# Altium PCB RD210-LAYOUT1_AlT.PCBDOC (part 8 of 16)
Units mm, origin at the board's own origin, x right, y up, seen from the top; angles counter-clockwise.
Board outline 330 x 300 mm, 6 copper layers (TOP, Mid-Layer 1, Mid-Layer 2, Mid-Layer 3, Mid-Layer 4, BOTTOM), stack 1.422 mm thick; 981 components, 463 nets, 2326 pads, 12534 vias.
Unrouted connection lines stored in the file: 6.
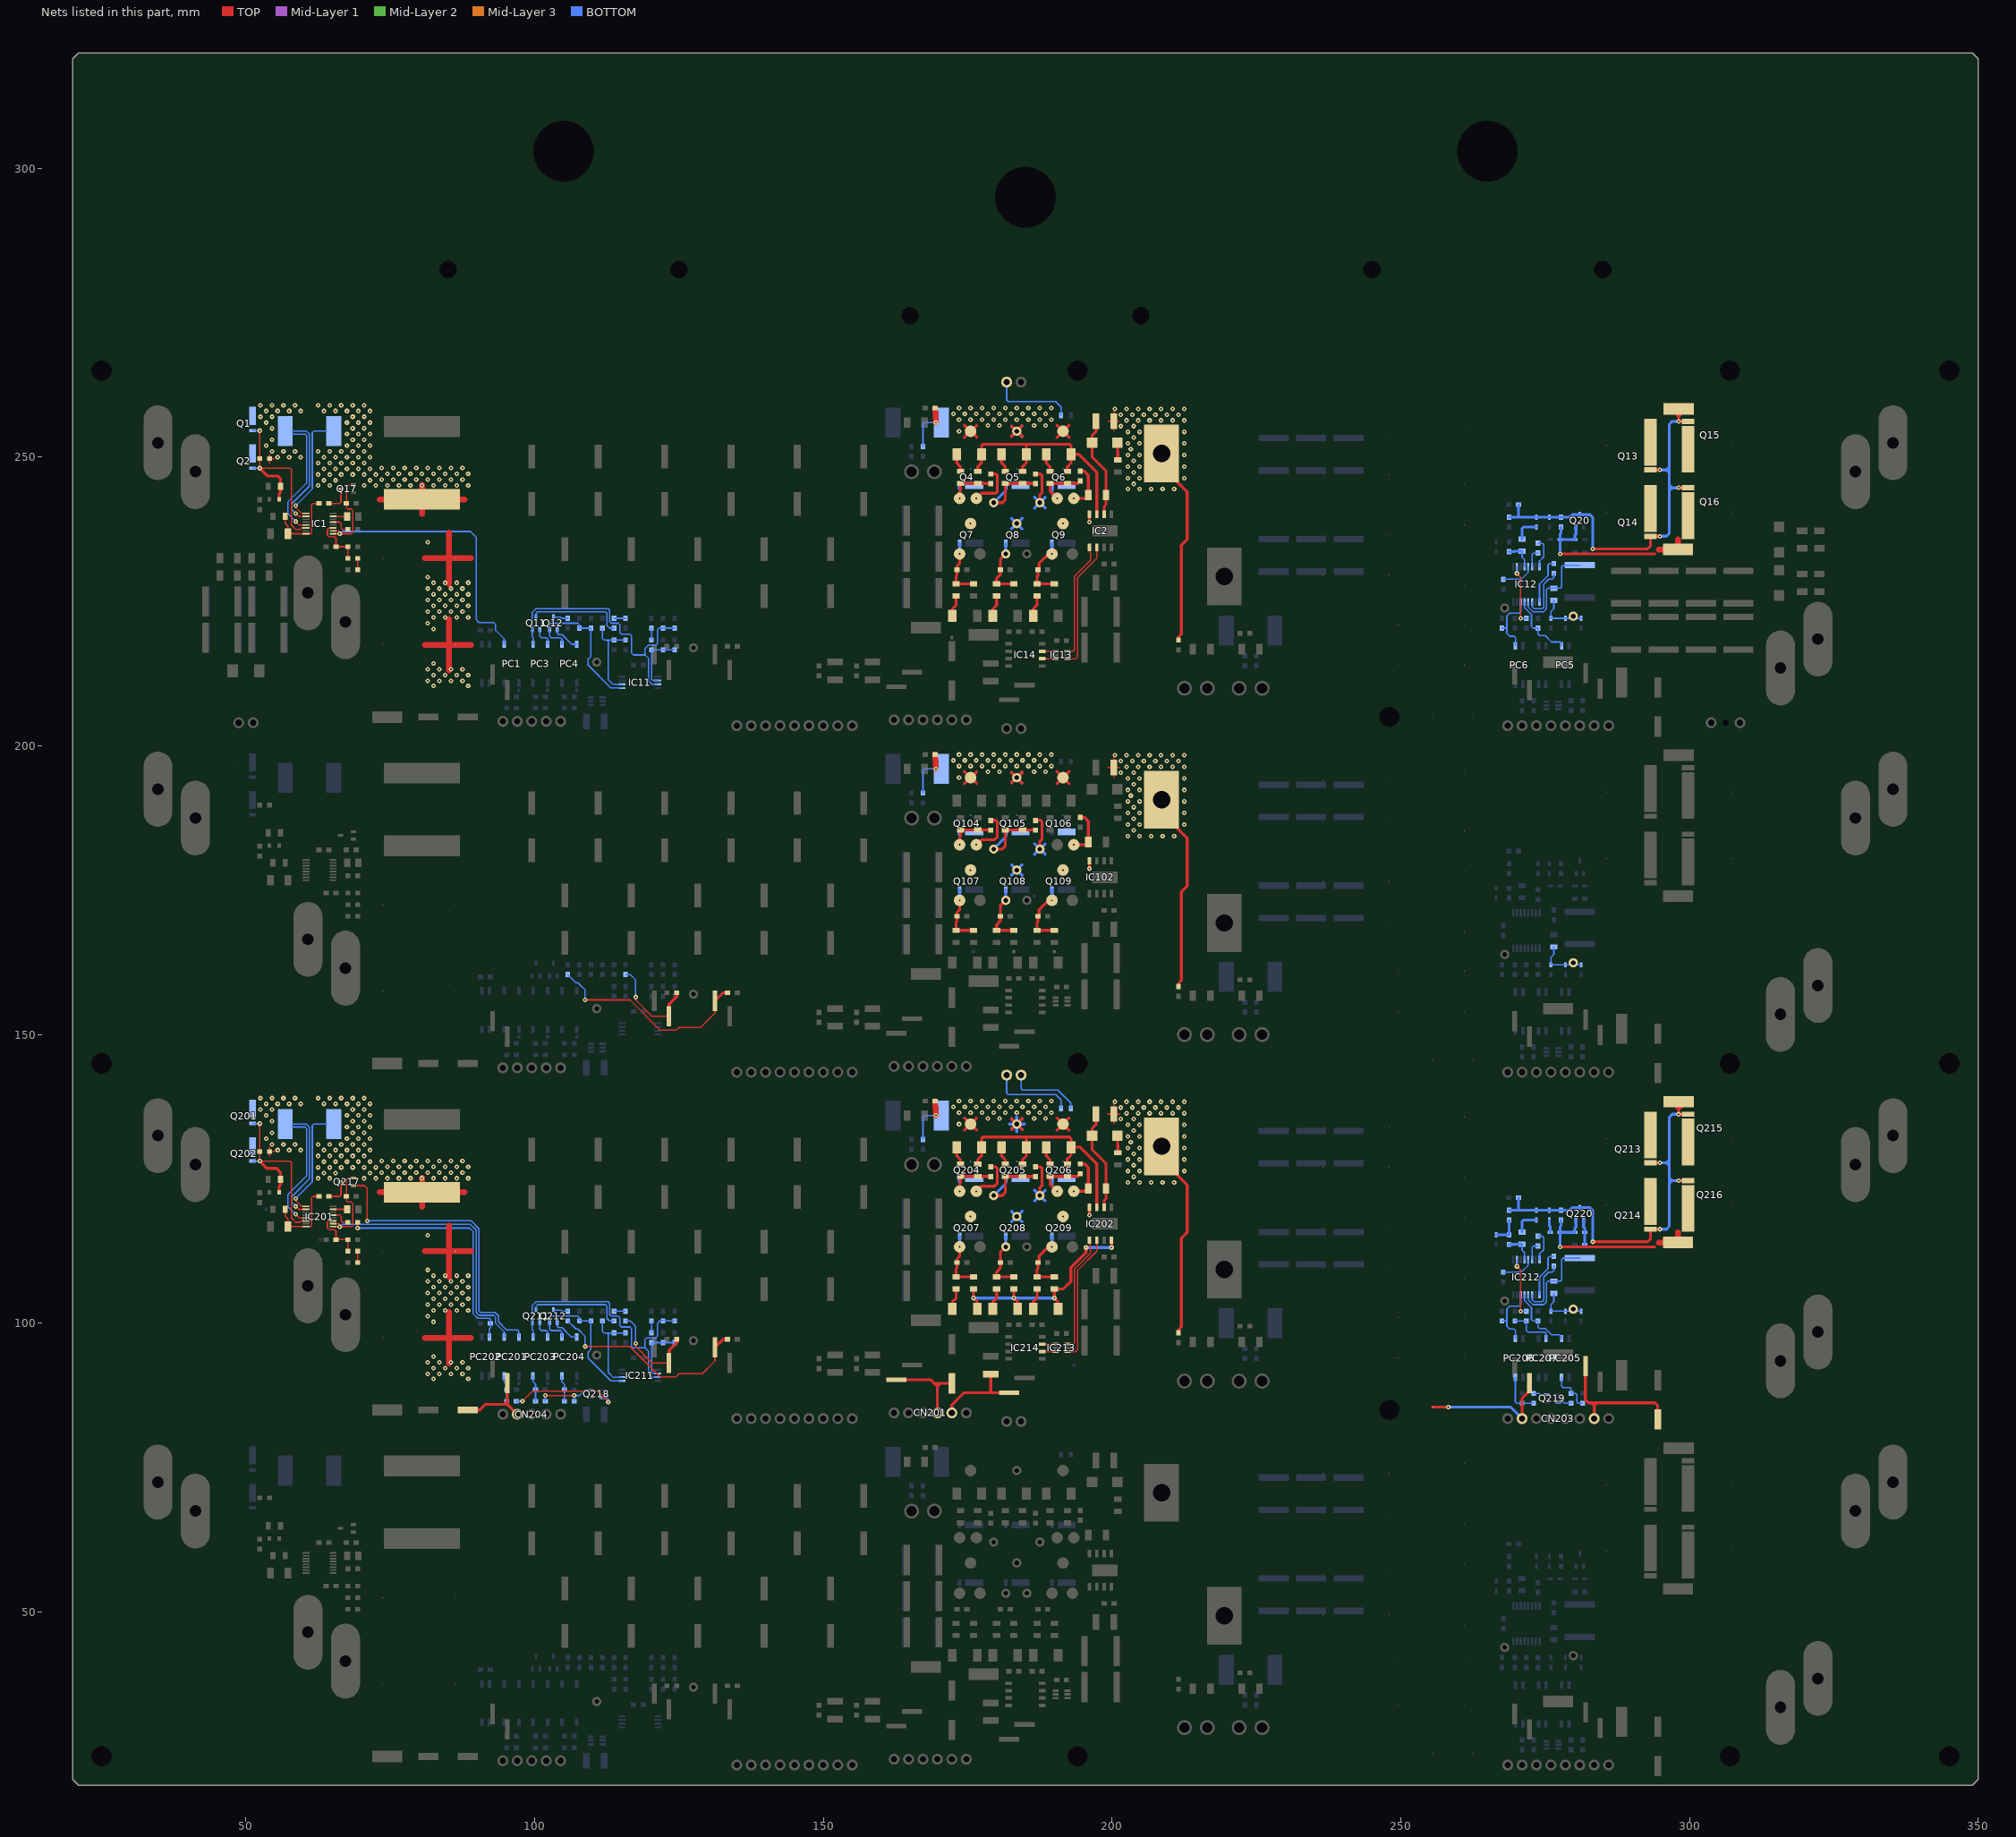
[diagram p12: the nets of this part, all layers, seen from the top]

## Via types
v1: diameter 0.8, hole 0.3, TOP to BOTTOM, 12534 vias

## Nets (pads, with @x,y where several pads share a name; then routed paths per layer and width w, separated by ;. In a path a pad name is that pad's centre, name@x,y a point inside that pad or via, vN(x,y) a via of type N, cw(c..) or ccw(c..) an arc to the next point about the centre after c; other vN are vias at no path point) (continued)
N00100195: C41.2 C436.2 CN31.1 CN33.1 IC2.4 L2.1 Q4.S Q5.S Q6.S Q7.D Q8.D Q9.D R12.2 R15.2 R18.2 R403.1 TP7.1 TP9.1 TP14.1 TP16.1 | length 74
  TOP w0.25: 199.325,256.25 C41.2@200.275,256.25 ; 200.275,254.525 C41.2@200.275,256.25 ; 200.275,257.975 C41.2@200.275,256.25 ; 201.225,256.25 C41.2@200.275,256.25
  TOP w0.5: v1(176.5,242.875) 177.375,243.75 179.875,243.75 180.125,244 180.125,246.85 179.875,247.1 R12.2@179,247.1 ; R15.2@186.75,247.1 187.625,247.1 187.875,246.85 187.875,243.875 187.5,243.5 CN31.1@187.5,242.125 ; v1(193.375,242.875) 195.343,242.875 C436.2@195.894,243.426 195.894,246.856 195.15,247.6 R18.2@194.5,247.6 ; v1(196.095,238.75) IC2.4@196.095,240.1 ; L2.1@208.566,248.434 213,244 213,235.75 212,234.75 212,219.375 211.5,218.875 R403.1@211.5,218.35
  TOP w1: L2.1@208.566,248.434 L2.1@208.566,250.664
  BOTTOM w0.5: 182.581,237.581 CN33.1@183.5,238.5 ; 182.581,239.419 CN33.1@183.5,238.5 ; 184.419,237.581 CN33.1@183.5,238.5 ; 184.419,239.419 CN33.1@183.5,238.5 ; 186.581,241.206 CN31.1@187.5,242.125 ; 186.581,243.044 CN31.1@187.5,242.125 ; 188.419,241.206 CN31.1@187.5,242.125 ; 188.419,243.044 CN31.1@187.5,242.125
  other v1: 175.5,238.5 191.5,238.5 202.75,244.5 204.75,244.5 206.75,244.5 208.75,244.5 210.75,244.5 203.75,245.375 202.75,246.375 204.75,246.375 212.5,246.375 203.75,247.375 202.75,248.375 204.75,248.375 212.5,248.375 203.75,249.375 202.75,250.375 204.75,250.375 212.5,250.375 203.25,251.375 202.75,252.375 204.75,252.375 212.5,252.375 203.75,253.375 202.75,254.375 204.75,254.375 212.5,254.375 201.5,255.375 203.75,255.375 202.5,256.375 204.5,256.375 206.5,256.375 208.5,256.375 210.5,256.375 212.5,256.375 201.5,257.375 203.5,257.375 205.5,257.375 207.5,257.375 209.5,257.375 211.5,257.375 200.5,258.375 202.5,258.375 204.5,258.375 206.5,258.375 208.5,258.375 210.5,258.375 212.5,258.375
N00200003: CN123.1 D111.2 D112.2 D113.2 R160.1 | length 8.8
  BOTTOM w0.25: R160.1@276.5,165.2 276.5,163.875 276,163.375 D111.2@276,162.1 D112.2@278.5,162.1 279.525,162.1 CN123.1@279.875,162.45 280.225,162.1 D113.2@281.25,162.1
N00200011: CN119.2 R147.1 R148.1 | length 17.2
  TOP w0.25: v1(117.5,156.5) 117.5,156 120.35,153.15 CN119.2@123.27,153.15
  TOP w0.5: CN119.2@123.27,153.15 123.27,155.27 124.6,156.6 R147.1@124.6,157.25
  BOTTOM w0.25: R148.1@115.75,160.4 116.6,160.4 117.5,159.5 v1(117.5,156.5)
N00200012: CN118.2 R155.1 R156.1 | length 36.6
  TOP w0.25: v1(108.75,156) 116.5,156 121.75,150.75 124.5,150.75 125,151.25 128.75,151.25 131.23,153.73 CN118.2@131.23,155.85
  TOP w0.5: CN118.2@131.23,155.85 132.63,157.25 R155.1@133.4,157.25
  BOTTOM w0.25: R156.1@105.75,160.4 105.75,160.375 107.125,159 107.5,159 108.75,157.75 v1(108.75,156)
N00200017: C141.2 C437.2 CN131.1 CN133.1 IC102.4 L102.1 Q104.S Q105.S Q106.S Q107.D Q108.D Q109.D R112.2 R115.2 R118.2 R413.1 TP107.1 TP109.1 TP114.1 TP116.1 | length 74
  TOP w0.25: 199.325,196.25 C141.2@200.275,196.25 ; 200.275,194.525 C141.2@200.275,196.25 ; 200.275,197.975 C141.2@200.275,196.25 ; 201.225,196.25 C141.2@200.275,196.25
  TOP w0.5: v1(176.5,182.875) 177.375,183.75 179.625,183.75 180.125,184.25 180.125,186.85 179.875,187.1 R112.2@179,187.1 ; R115.2@186.75,187.1 187.625,187.1 187.875,186.85 187.875,183.875 187.5,183.5 CN131.1@187.5,182.125 ; v1(193.375,182.875) 195.414,182.875 C437.2@195.894,183.355 195.894,186.966 195.26,187.6 R118.2@194.5,187.6 ; v1(196.095,178.75) IC102.4@196.095,180.1 ; L102.1@208.566,190.664 208.566,188.434 213,184 213,175.75 212,174.75 212,159.375 211.5,158.875 R413.1@211.5,158.35
  BOTTOM w0.5: 182.581,177.581 CN133.1@183.5,178.5 ; 182.581,179.419 CN133.1@183.5,178.5 ; 184.419,177.581 CN133.1@183.5,178.5 ; 184.419,179.419 CN133.1@183.5,178.5 ; 186.581,181.206 CN131.1@187.5,182.125 ; 186.581,183.044 CN131.1@187.5,182.125 ; 188.419,181.206 CN131.1@187.5,182.125 ; 188.419,183.044 CN131.1@187.5,182.125
  other v1: 175.5,178.5 191.5,178.5 202.75,184.375 204.75,184.375 206.75,184.375 208.75,184.375 210.75,184.375 203.75,185.375 202.75,186.375 204.75,186.375 212.5,186.375 203.75,187.375 202.75,188.375 204.75,188.375 212.5,188.375 203.75,189.375 202.75,190.375 204.75,190.375 212.5,190.375 203.25,191.375 202.75,192.375 204.75,192.375 212.5,192.375 203.75,193.375 202.75,194.375 204.75,194.375 212.5,194.375 201.5,195.375 203.75,195.375 202.5,196.375 204.5,196.375 206.5,196.375 208.5,196.375 210.5,196.375 212.5,196.375 201.5,197.375 203.5,197.375 205.5,197.375 207.5,197.375 209.5,197.375 211.5,197.375 200.5,198.375 202.5,198.375 204.5,198.375 206.5,198.375 208.5,198.375 210.5,198.375 212.5,198.375
N00200022: Q104.G R110.2 R111.2 R112.1 TP124.1 | length 10.1
  TOP w0.5: v1(173.595,182.875) 173.595,184.155 173.75,184.31 R110.2@173.75,185.45 R111.2@176.75,185.45 178.95,185.45 R112.1@179,185.4
  BOTTOM w0.5: v1(173.595,182.875) Q104.G@173.595,185.1
N00200025: C142.1 CN130.1 Q104.D Q105.D Q106.D R129.2 R411.1 TP104.1 TP106.1 | length 46.8
  TOP w0.5: 174.439,193.439 TP104.1@175.5,194.5 ; 174.439,195.561 TP104.1@175.5,194.5 ; 176.561,193.439 TP104.1@175.5,194.5 ; 176.561,195.561 TP104.1@175.5,194.5 ; 182.581,193.581 CN130.1@183.5,194.5 ; 182.581,195.419 CN130.1@183.5,194.5 ; 184.419,193.581 CN130.1@183.5,194.5 ; 184.419,195.419 CN130.1@183.5,194.5 ; 190.439,193.439 TP106.1@191.5,194.5 ; 190.439,195.561 TP106.1@191.5,194.5 ; 192.561,193.439 TP106.1@191.5,194.5 ; 192.561,195.561 TP106.1@191.5,194.5
  TOP w1: R411.1@169.35,198.5 169.35,197.65 169.5,197.5 v1(169.5,196)
  Mid-Layer 1 w0.5: 182.581,193.581 CN130.1@183.5,194.5 ; 182.581,195.419 CN130.1@183.5,194.5 ; 184.419,193.581 CN130.1@183.5,194.5 ; 184.419,195.419 CN130.1@183.5,194.5
  Mid-Layer 2 w0.5: 182.581,193.581 CN130.1@183.5,194.5 ; 182.581,195.419 CN130.1@183.5,194.5 ; 184.419,193.581 CN130.1@183.5,194.5 ; 184.419,195.419 CN130.1@183.5,194.5
  Mid-Layer 3 w0.5: 182.581,193.581 CN130.1@183.5,194.5 ; 182.581,195.419 CN130.1@183.5,194.5 ; 184.419,193.581 CN130.1@183.5,194.5 ; 184.419,195.419 CN130.1@183.5,194.5
  BOTTOM w0.25: C142.1@167.25,191.85 167.25,195.75 167.5,196 v1(169.5,196)
  BOTTOM w0.5: 182.581,193.581 CN130.1@183.5,194.5 ; 182.581,195.419 CN130.1@183.5,194.5 ; 184.419,193.581 CN130.1@183.5,194.5 ; 184.419,195.419 CN130.1@183.5,194.5
  other v1: 173.5,194.5 178.5,195.5 180.5,195.5 186.5,195.5 188.5,195.5 173.5,196.5 175.5,196.5 177.5,196.5 179.5,196.5 181.5,196.5 183.5,196.5 185.5,196.5 187.5,196.5 189.5,196.5 172.5,197.5 174.5,197.5 176.5,197.5 178.5,197.5 180.5,197.5 182.5,197.5 184.5,197.5 186.5,197.5 188.5,197.5 173.5,198.5 175.5,198.5 177.5,198.5 179.5,198.5 181.5,198.5 183.5,198.5 185.5,198.5 187.5,198.5 189.5,198.5
N00200030: CN129.1 Q105.G R113.2 R114.2 R115.1 | length 14.1
  TOP w0.5: CN129.1@179.5,182.125 181,182.125 181.5,182.625 R113.2@181.5,185.45 R114.2@184.5,185.45 186.7,185.45 R115.1@186.75,185.4
  BOTTOM w0.5: CN129.1@179.5,182.125 181.595,184.22 Q105.G@181.595,185.1
N00200031: CN132.1 Q108.G R123.2 R124.2 R125.1 | length 10.7
  TOP w0.5: CN132.1@181.595,173.25 180.65,172.305 R125.1@180.65,170.5 180.65,169.65 180,169 R123.2@180,168.05 R124.2@183,168.05
  BOTTOM w0.5: CN132.1@181.595,173.25 Q108.G@181.595,175.1
N00200032: Q109.G R126.2 R127.2 R128.1 TP129.1 | length 11.5
  TOP w0.5: v1(189.595,173.25) 189,173.25 187.375,171.625 187.375,170.725 R128.1@187.15,170.5 187.15,169.5 187,169.35 R126.2@187,168.05 R127.2@190,168.05
  BOTTOM w0.5: v1(189.595,173.25) Q109.G@189.595,175.1
N00200033: Q107.G R120.2 R121.2 R122.1 TP127.1 | length 10.3
  TOP w0.5: v1(173.595,173.25) 173.595,171.595 173.15,171.15 R122.1@173.15,170.5 173.15,169.65 173,169.5 R120.2@173,168.05 R121.2@176,168.05
  BOTTOM w0.5: v1(173.595,173.25) Q107.G@173.595,175.1
N00300003: CN223.1 D211.2 D212.2 D213.2 R260.1 | length 8.8
  BOTTOM w0.25: R260.1@276.5,105.2 276.5,103.75 276,103.25 D211.2@276,102.1 D212.2@278.5,102.1 279.525,102.1 CN223.1@279.875,102.45 280.225,102.1 D213.2@281.25,102.1
N00300004: Q206.G R216.2 R217.2 R218.1 TP226.1 | length 11.1
  TOP w0.5: v1(190.5,122.875) 189.25,124.125 R216.2@189.25,125.45 R217.2@192.25,125.45 194.05,125.45 R218.1@194.5,125.9
  BOTTOM w0.5: Q206.G@189.595,125.1 189.595,123.78 v1(190.5,122.875)
N00300015: C211.2 IC211.3 PC203.4 Q211.2 R250.1 | length 48.7
  BOTTOM w0.25: PC203.4@99.73,97.6 99.73,98.75 99.6,98.88 Q211.2@99.6,100.15 99.6,103.1 100.25,103.75 112.75,103.75 113,103.5 113,101.5 113.25,101.25 114.5,101.25 114.75,101 114.75,99.625 115,99.375 116.5,99.375 116.75,99.125 116.75,96 117,95.75 118.875,95.75 ; IC211.3@121.35,90.675 120.325,90.675 119.75,91.25 119.75,95.125 119.125,95.75 ; R250.1@124.25,100.4 C211.2@122.25,100.4 121.65,100.4 121.25,100 121.25,97.75 121,97.5 119.375,97.5 119.125,97.25 119.125,96 ; 118.875,95.75 119.125,96 ; 118.875,95.75 119.125,95.75 ; 119.125,95.75 119.125,96
N00300018: C279.2 IC211.5 PC204.4 Q212.2 R257.1 | length 27.4
  BOTTOM w0.25: PC204.4@104.73,97.6 104.73,98.5 104.48,98.75 102.85,98.75 102.6,99 Q212.2@102.6,100.15 102.6,101 102.85,101.25 107.5,101.25 107.75,101 C279.2@107.75,100.4 108.95,100.4 108.975,100.375 109,100.4 R257.1@109.75,100.4 109.75,95.5 109.25,95 109.25,94 113.225,90.025 IC211.5@115.15,90.025
N00300019: Q4.G R10.2 R11.2 R12.1 TP24.1 | length 10.1
  TOP w0.5: v1(173.595,242.875) 173.595,244.155 173.75,244.31 R10.2@173.75,245.45 R11.2@176.75,245.45 178.95,245.45 R12.1@179,245.4
  BOTTOM w0.5: v1(173.595,242.875) Q4.G@173.595,245.1
N00300025: C276.1 IC211.2 R252.2 R253.1 | length 10.3
  BOTTOM w0.25: IC211.2@121.35,91.325 120.5,91.325 120.25,91.575 R252.2@120.25,96.65 C276.1@122.25,96.65 R253.1@124.25,96.65
N00300029: C280.1 IC211.6 R258.2 R259.1 | length 16
  BOTTOM w0.25: R258.2@111.75,100.4 111.75,98.6 112,98.35 112.5,98.35 ; IC211.6@115.15,90.675 113.575,90.675 112.75,91.5 112.75,98.1 ; R259.1@115.75,98.35 C280.1@113.75,98.35 113,98.35 ; 112.5,98.35 112.75,98.1 ; 112.5,98.35 113,98.35 ; 112.75,98.1 113,98.35
N00300031: C213.2 IC201.8 R201.1 R264.2 | length 13.6
  TOP w0.25: R201.1@56.8,119.75 56.8,118.575 57.275,118.1 C213.2@57.275,116.75 IC201.8@60.4,116.75 61.25,116.75 61.375,116.875 61.375,121.75 61.625,122 R264.2@62.65,122
N00300035: IC202.5 IC213.6 | length 20.3
  TOP w0.25: IC213.6@192.275,96.4 193.25,96.4 193.5,96.65 193.5,109.375 196.25,112.125 196.25,113.375 196.095,113.53 IC202.5@196.095,114.4
N00300036: D202.2 D203.2 D204.2 IC202.3 R211.1 R214.1 R217.1 | length 43.8
  TOP w0.5: R211.1@176.75,127.55 176.75,128.35 177.4,129 D202.2@177.4,130.5 177.4,132 177.65,132.25 184.9,132.25 ; R214.1@184.5,127.55 184.5,128.35 185.15,129 D203.2@185.15,130.5 185.15,132 ; R217.1@192.25,127.55 192.25,128.475 192.9,129.125 D204.2@192.9,130.5 ; IC202.3@197.365,120.1 197.365,127.635 194.5,130.5 D204.2@192.9,130.5 ; 184.9,132.25 185.15,132 ; 184.9,132.25 185.4,132.25 ; 185.15,132 185.4,132.25 ; 185.4,132.25 192.65,132.25 192.9,132 D204.2@192.9,130.5
N00300037: D206.2 D207.2 D208.2 IC202.8 R221.1 R224.1 R227.1 | length 41.2
  TOP w0.5: R221.1@176,105.95 v1(176,104.375) 176.65,103.725 D206.2@176.65,102.5 ; R224.1@183,105.95 v1(183,104.375) 183.65,103.725 D207.2@183.65,102.5 ; D208.2@190.65,102.5 190.65,103.725 v1(190,104.375) R227.1@190,105.95 191.575,105.95 192.875,107.25 192.875,109.625 195.5,112.25 v1(195.5,113.125) ; v1(199.905,113.125) IC202.8@199.905,114.4
  BOTTOM w0.5: v1(176,104.375) v1(183,104.375) v1(190,104.375) ; v1(195.5,113.125) v1(199.905,113.125)
N00300038: C241.1 C438.1 D205.2 IC202.2 | length 17.5
  TOP w0.5: C241.1@197.225,136.25 197.225,134.425 196.55,133.75 D205.2@196.55,132.5 196.55,130.075 198.944,127.681 C438.1@198.944,123.347 198.944,121.561 198.635,121.252 IC202.2@198.635,120.1
N00300039: IC202.6 IC213.4 | length 22.3
  TOP w0.25: IC213.4@192.275,95.1 193.75,95.1 194,95.35 194,109.125 197.365,112.49 IC202.6@197.365,114.4
N00300040: C214.1 IC201.15 | length 2.4
  TOP w0.25: IC201.15@65.1,119.75 C214.1@67.525,119.75
N00300044: CN219.2 R247.1 R248.1 | length 17.2
  TOP w0.25: v1(117.5,96.5) 117.5,96 120.35,93.15 CN219.2@123.27,93.15
  TOP w0.5: CN219.2@123.27,93.15 123.27,95.27 124.6,96.6 R247.1@124.6,97.25
  BOTTOM w0.25: R248.1@115.75,100.4 116.6,100.4 117.5,99.5 v1(117.5,96.5)
N00300045: CN218.2 R255.1 R256.1 | length 36.8
  TOP w0.25: v1(108.75,96) 116.471,96 121.736,90.736 124.486,90.736 125,91.25 129,91.25 131.23,93.48 CN218.2@131.23,95.85
  TOP w0.5: CN218.2@131.23,95.85 132.63,97.25 R255.1@133.4,97.25
  BOTTOM w0.25: R256.1@105.75,100.4 107.15,99 107.5,99 108.75,97.75 v1(108.75,96)
N00300046: C216.1 C217.1 IC201.1 L201.1 R208.2 | length 72.6
  TOP w0.25: v1(58.625,121.625) 58.625,121.25 59.625,120.25 IC201.1@60.4,120.25
  TOP w1: 73.15,122.7 L201.1@80.5,122.7 ; 80.5,120.15 L201.1@80.5,122.7 ; v1@80.5,125.25 v1(80.5,125.125) L201.1@80.5,122.7 ; 81,97.5 85.15,97.5 ; 81,112.5 85.15,112.5 ; 85.15,93.043 85.15,97.5 ; 85.15,101.957 85.15,97.5 ; 85.15,108.043 85.15,112.5 ; 85.15,116.957 85.15,112.5 ; 87.85,122.7 L201.1@80.5,122.7 ; 89,97.5 C217.1@86.3,97.5 85.15,97.5 ; 89,112.5 C216.1@86.3,112.5 85.15,112.5
  BOTTOM w0.25: v1(58.625,121.625) 61.5,124.5 61.5,134.25 61.75,134.5 R208.2@64,134.5
  other v1: 82.5,90.375 88.5,90.375 81.5,91.25 83.5,91.25 85.5,91.25 87.5,91.25 82.5,92.25 84.5,92.25 86.5,92.25 88.5,92.25 81.5,93.25 83.5,93.25 85.5,93.25 87.5,93.25 82.5,94.25 82.5,100.25 81.5,101.25 82.5,102.25 84.5,102.25 86.5,102.25 88.5,102.25 81.5,103.25 83.5,103.25 85.5,103.25 87.5,103.25 82.5,104.25 84.5,104.25 86.5,104.25 88.5,104.25 81.5,105.25 83.5,105.25 85.5,105.25 87.5,105.25 82.5,106.25 84.5,106.25 86.5,106.25 88.5,106.25 81.5,107.25 83.5,107.25 85.5,107.25 87.5,107.25 82.5,108.25 84.5,108.25 86.5,108.25 88.5,108.25 81.5,109.25 81.5,115.25 62.5,125.125 64.5,125.125 70.5,125.125 72.5,125.125 74.5,125.125 76.5,125.125 78.5,125.125 82.5,125.125 84.5,125.125 86.5,125.125 88.5,125.125 63.5,126 65.5,126 71.5,126 73.5,126.125 75.5,126.125 77.5,126.125 79.5,126.125 81.5,126.125 83.5,126.125 85.5,126.125 87.5,126.125 62.5,127 64.5,127 66.5,127 68.5,127 70.5,127 72.5,127 74.5,127.125 76.5,127.125 78.5,127.125 80.5,127.125 82.5,127.125 84.5,127.125 86.5,127.125 88.5,127.125 63.5,128 65.5,128 67.5,128 69.5,128 71.5,128 73.5,128.125 75.5,128.125 77.5,128.125 79.5,128.125 81.5,128.125 83.5,128.125 85.5,128.125 87.5,128.125 62.5,129 64.5,129 66.5,129 68.5,129 70.5,129 63.5,130 65.5,130 67.5,130 69.5,130 71.5,130 62.5,131 64.5,131 66.5,131 68.5,131 70.5,131 67.5,132 69.5,132 71.5,132 68.5,133 70.5,133 67.5,134 69.5,134 71.5,134 68.5,135 70.5,135 67.5,136 69.5,136 71.5,136 68.5,137 70.5,137 63.5,138 65.5,138 67.5,138 69.5,138 71.5,138 62.5,139 64.5,139 66.5,139 68.5,139 70.5,139
N00300047: IC201.2 IC201.5 Q201.S Q202.S R207.2 R208.1 | length 44.3
  TOP w0.25: 54.1,128.975 R207.2@54.1,129.75 ; 54.1,130.525 R207.2@54.1,129.75 ; 54.925,129.75 R207.2@54.1,129.75 ; v1(58.625,118.875) 59.25,118.25 IC201.5@60.4,118.25 ; v1(58.625,120.25) 59.125,119.75 IC201.2@60.4,119.75
  BOTTOM w0.25: R208.1@58,134 60.25,134 60.5,133.75 60.5,125.5 57.25,122.25 57.25,120.25 v1(58.625,118.875) ; R208.1@58,134.5 60.5,134.5 61,134 61,125 57.875,121.875 57.875,121 v1(58.625,120.25)
  other v1: 55.5,130 57.5,130 59.5,130 54.5,131 56.5,131 58.5,131 53.5,132 54.5,133 54.5,135 53.5,136 52.5,137 54.5,137 53.5,138 55.5,138 57.5,138 59.5,138 52.5,139 54.5,139 56.5,139 58.5,139
N00300048: D324.2 IC201.6 Q201.G Q202.G R207.1 R436.1 | length 35
  TOP w0.25: v1(52.4,134.595) R207.1@52.4,129.75 v1(52.4,128.095) 57.625,128.095 57.875,127.845 57.875,118.25 58.625,117.5 59.375,117.5 59.625,117.75 IC201.6@60.4,117.75
  TOP w0.5: v1(52.4,128.095) 53.655,126.84 55.306,126.84 55.975,126.171 R436.1@55.975,124.935 55.975,123.992 55.775,123.792 D324.2@55.775,122.712
  BOTTOM w0.25: Q202.G@51.15,128.095 v1(52.4,128.095) ; Q201.G@51.15,134.595 v1(52.4,134.595)
N00300049: D207.1 R223.1 | length 3.7
  TOP w0.5: D207.1@179.35,102.5 179.35,103.725 180,104.375 R223.1@180,105.95
N00300050: D205.1 R209.2 | length 3
  TOP w0.5: D205.1@200.95,132.5 200.95,131 201,130.95 R209.2@201,129.55
N00300051: D202.1 R210.1 | length 3.2
  TOP w0.5: D202.1@173.1,130.5 173.1,129 173.75,128.35 R210.1@173.75,127.55
N00300053: D203.1 R213.1 | length 3.2
  TOP w0.5: D203.1@180.85,130.5 180.85,129 181.5,128.35 R213.1@181.5,127.55
N00300054: D204.1 R216.1 | length 3.2
  TOP w0.5: D204.1@188.6,130.5 188.6,129 189.25,128.35 R216.1@189.25,127.55
N00300055: D206.1 R220.1 | length 3.7
  TOP w0.5: D206.1@172.35,102.5 172.35,103.725 173,104.375 R220.1@173,105.95
N00300056: D208.1 R226.1 | length 3.7
  TOP w0.5: D208.1@186.35,102.5 186.35,103.725 187,104.375 R226.1@187,105.95
N00300062: C241.2 C438.2 CN231.1 CN233.1 IC202.4 L202.1 Q204.S Q205.S Q206.S Q207.D Q208.D Q209.D R212.2 R215.2 R218.2 R423.1 TP207.1 TP209.1 TP214.1 TP216.1 | length 74
  TOP w0.25: 199.325,136.25 C241.2@200.275,136.25 ; 200.275,134.525 C241.2@200.275,136.25 ; 200.275,137.975 C241.2@200.275,136.25 ; 201.225,136.25 C241.2@200.275,136.25
  TOP w0.5: v1(176.5,122.875) 177.375,123.75 179.625,123.75 180.125,124.25 180.125,126.85 179.875,127.1 R212.2@179,127.1 ; R215.2@186.75,127.1 187.625,127.1 187.875,126.85 187.875,123.875 187.5,123.5 CN231.1@187.5,122.125 ; v1(193.375,122.875) 195.422,122.875 C438.2@195.894,123.347 195.894,126.968 195.262,127.6 R218.2@194.5,127.6 ; v1(196.095,118.75) IC202.4@196.095,120.1 ; L202.1@208.566,130.664 208.566,128.434 213,124 213,115.75 212,114.75 212,99.375 211.5,98.875 R423.1@211.5,98.35
  BOTTOM w0.5: 182.581,117.581 CN233.1@183.5,118.5 ; 182.581,119.419 CN233.1@183.5,118.5 ; 184.419,117.581 CN233.1@183.5,118.5 ; 184.419,119.419 CN233.1@183.5,118.5 ; 186.581,121.206 CN231.1@187.5,122.125 ; 186.581,123.044 CN231.1@187.5,122.125 ; 188.419,121.206 CN231.1@187.5,122.125 ; 188.419,123.044 CN231.1@187.5,122.125
  other v1: 175.5,118.5 191.5,118.5 202.75,124.375 204.75,124.375 206.75,124.375 208.75,124.375 210.75,124.375 203.75,125.375 202.75,126.375 204.75,126.375 212.5,126.375 203.75,127.375 202.75,128.375 204.75,128.375 212.5,128.375 203.75,129.375 202.75,130.375 204.75,130.375 212.5,130.375 203.25,131.375 202.75,132.375 204.75,132.375 212.5,132.375 203.75,133.375 202.75,134.375 204.75,134.375 212.5,134.375 201.5,135.375 203.75,135.375 202.5,136.375 204.5,136.375 206.5,136.375 208.5,136.375 210.5,136.375 212.5,136.375 201.5,137.375 203.5,137.375 205.5,137.375 207.5,137.375 209.5,137.375 211.5,137.375 200.5,138.375 202.5,138.375 204.5,138.375 206.5,138.375 208.5,138.375 210.5,138.375 212.5,138.375
N00300064: C442.1 CN221.1 D219.1 D220.1 Q213.1 Q214.1 Q215.1 Q216.1 Q220.3 R263.2 R292.2 | length 75.2
  TOP w0.5: v1(283.25,114.125) 292.75,114.125 293.25,114.625 Q214.1@293.25,116.3 v1(294.875,116.3) ; Q213.1@293.25,127.8 v1(294.875,127.8) ; v1(298.125,124.7) Q216.1@299.75,124.7 ; Q215.1@299.75,136.2 v1(298.125,136.2) 298.125,137 ; 298.125,137 CN221.1@298.125,138.375 ; 298.125,137 297.5,137.625 297.5,138.375 CN221.1@298.125,138.375 ; 298.125,137 298.75,137.625 298.75,138.375 CN221.1@298.125,138.375
  BOTTOM w0.5: R292.2@268.75,119.6 270.405,119.6 ; C442.1@270.405,121.775 270.405,119.6 ; v1(283.25,114.125) 283.25,119.55 282.75,120.05 279.7,120.05 279.25,119.6 R263.2@277.75,119.6 D219.1@275.75,119.6 D220.1@273.5,119.6 270.405,119.6 ; v1(294.875,116.3) 296,116.3 296.5,116.8 296.5,124.2 ; v1(294.875,127.8) 296,127.8 ; v1(298.125,124.7) 297,124.7 ; v1(298.125,136.2) 297,136.2 296.5,135.7 296.5,128.3 ; 296,127.8 296.5,128.3 ; 296,127.8 296.5,127.3 ; 296.5,124.2 296.5,125.2 ; 296.5,124.2 297,124.7 ; 296.5,125.2 296.5,127.3 ; 296.5,125.2 297,124.7 ; 296.5,127.3 296.5,128.3
N00300065: CN222.1 D218.1 D221.1 Q213.2 Q214.2 Q215.2 Q216.2 Q220.2 R263.1 | length 31
  TOP w0.5: v1(277.6,113.25) 294,113.25
  TOP w1: 294.65,114 CN222.1@298,114 298,115.75
  BOTTOM w0.5: v1(277.6,113.25) D221.1@277.6,115.75 ; R263.1@277.75,117.9 277.75,116.875 277.6,116.725 D221.1@277.6,115.75 ; Q220.2@280.35,117.95 Q220.2@280.35,117.9 280.35,116.7 280.15,116.5 D218.1@280.15,115.75 D221.1@277.6,115.75
N00300070: PC203.6 Q211.1 | length 3.7
  BOTTOM w0.25: Q211.1@100.9,100.2 Q211.1@100.9,100.15 100.9,99 101.15,98.75 102.02,98.75 102.27,98.5 PC203.6@102.27,97.6
N00300071: Q211.3 R249.2 | length 16.7
  BOTTOM w0.25: Q211.3@100.25,102.3 Q211.3@100.25,102.35 100.25,103 100.5,103.25 112.25,103.25 112.5,103 112.5,100.875 112.975,100.4 R249.2@113.75,100.4
N00300078: Q212.3 R256.2 | length 2.6
  BOTTOM w0.25: Q212.3@103.25,102.3 104.5,102.3 104.7,102.1 R256.2@105.75,102.1
N00300079: PC204.6 Q212.1 | length 4.9
  BOTTOM w0.25: Q212.1@103.9,100.2 Q212.1@103.9,100.15 103.9,99.5 104.15,99.25 104.75,99.25 106.4,97.6 PC204.6@107.27,97.6
N00300080: C215.2 IC201.11 R202.1 R203.2 | length 9.3
  TOP w0.25: IC201.11@65.1,117.75 64.375,117.75 64.125,117.5 64.125,116.5 64.375,116.25 65.35,116.25 65.6,116 R202.1@65.6,114.5 C215.2@67.65,114.5 R203.2@67.65,112.5
N00300081: IC201.9 IC201.10 PC201.4 Q217.2 R265.2 | length 61.2
  TOP w0.25: IC201.9@65.1,116.75 v1(66.25,116.75) ; IC201.10@65.1,117.25 66.125,117.25 66.25,117.125 v1(66.25,116.75) ; Q217.2@68.55,125.15 67.65,125.15 67.4,124.9 R265.2@67.4,122 67.4,121.25 67.65,121 68.25,121 68.5,120.75 68.5,117 68.25,116.75 v1(66.25,116.75)
  BOTTOM w0.25: v1(66.25,116.75) 66.625,117.125 88.875,117.125 89.875,116.125 89.875,101.875 90.375,101.375 92.875,101.375 93.25,101 93.25,100 94.73,98.52 PC201.4@94.73,97.6
N00300082: IC201.13 R270.1 | length 3.5
  TOP w0.25: IC201.13@65.1,118.75 66.25,118.75 66.5,118.5 66.5,117.75 66.75,117.5 R270.1@67.65,117.5
N00300090: C242.1 CN230.1 Q204.D Q205.D Q206.D R229.2 R421.1 TP204.1 TP206.1 | length 46.8
  TOP w0.5: 174.439,133.439 TP204.1@175.5,134.5 ; 174.439,135.561 TP204.1@175.5,134.5 ; 176.561,133.439 TP204.1@175.5,134.5 ; 176.561,135.561 TP204.1@175.5,134.5 ; 182.581,133.581 CN230.1@183.5,134.5 ; 182.581,135.419 CN230.1@183.5,134.5 ; 184.419,133.581 CN230.1@183.5,134.5 ; 184.419,135.419 CN230.1@183.5,134.5 ; 190.439,133.439 TP206.1@191.5,134.5 ; 190.439,135.561 TP206.1@191.5,134.5 ; 192.561,133.439 TP206.1@191.5,134.5 ; 192.561,135.561 TP206.1@191.5,134.5
  TOP w1: R421.1@169.35,138.5 169.35,137.65 169.5,137.5 v1(169.5,136)
  Mid-Layer 1 w0.5: 182.581,133.581 CN230.1@183.5,134.5 ; 182.581,135.419 CN230.1@183.5,134.5 ; 184.419,133.581 CN230.1@183.5,134.5 ; 184.419,135.419 CN230.1@183.5,134.5
  Mid-Layer 2 w0.5: 182.581,133.581 CN230.1@183.5,134.5 ; 182.581,135.419 CN230.1@183.5,134.5 ; 184.419,133.581 CN230.1@183.5,134.5 ; 184.419,135.419 CN230.1@183.5,134.5
  Mid-Layer 3 w0.5: 182.581,133.581 CN230.1@183.5,134.5 ; 182.581,135.419 CN230.1@183.5,134.5 ; 184.419,133.581 CN230.1@183.5,134.5 ; 184.419,135.419 CN230.1@183.5,134.5
  BOTTOM w0.25: C242.1@167.25,131.85 167.25,135.75 167.5,136 v1(169.5,136)
  BOTTOM w0.5: 182.2,134.5 CN230.1@183.5,134.5 ; 183.5,133.2 CN230.1@183.5,134.5 ; 183.5,135.8 CN230.1@183.5,134.5 ; 184.8,134.5 CN230.1@183.5,134.5
  other v1: 173.5,134.5 178.5,135.5 180.5,135.5 186.5,135.5 188.5,135.5 173.5,136.5 175.5,136.5 177.5,136.5 179.5,136.5 181.5,136.5 183.5,136.5 185.5,136.5 187.5,136.5 189.5,136.5 172.5,137.5 174.5,137.5 176.5,137.5 178.5,137.5 180.5,137.5 182.5,137.5 184.5,137.5 186.5,137.5 188.5,137.5 173.5,138.5 175.5,138.5 177.5,138.5 179.5,138.5 181.5,138.5 183.5,138.5 185.5,138.5 187.5,138.5 189.5,138.5
N00300091: CN232.1 Q208.G R223.2 R224.2 R225.1 | length 10.7
  TOP w0.5: CN232.1@181.595,113.25 180.65,112.305 R225.1@180.65,110.5 180.65,109.525 180,108.875 R223.2@180,108.05 R224.2@183,108.05
  BOTTOM w0.5: CN232.1@181.595,113.25 Q208.G@181.595,115.1
N00300092: CN229.1 Q205.G R213.2 R214.2 R215.1 | length 14.1
  TOP w0.5: CN229.1@179.5,122.125 181,122.125 181.5,122.625 R213.2@181.5,125.45 R214.2@184.5,125.45 186.7,125.45 R215.1@186.75,125.4
  BOTTOM w0.5: CN229.1@179.5,122.125 181.595,124.22 Q205.G@181.595,125.1
N00300095: D220.2 R282.2 | length 4.5
  BOTTOM w0.5: R282.2@271,115.8 271,117.65 271.25,117.9 D220.2@273.5,117.9
N00300096: IC212.12 R281.1 R282.1 | length 5.1
  BOTTOM w0.25: R282.1@271,113.7 271,112.675 271.425,112.25 IC212.12@271.425,111.05
  BOTTOM w0.5: R281.1@268.75,113.65 269.75,113.65 269.8,113.7 R282.1@271,113.7
N00300097: Q204.G R210.2 R211.2 R212.1 TP224.1 | length 10.1
  TOP w0.5: v1(173.595,122.875) 173.595,124.155 173.75,124.31 R210.2@173.75,125.45 R211.2@176.75,125.45 178.95,125.45 R212.1@179,125.4
  BOTTOM w0.5: v1(173.595,122.875) Q204.G@173.595,125.1
N00300099: Q209.G R226.2 R227.2 R228.1 TP229.1 | length 11.5
  TOP w0.5: v1(189.595,113.25) 189,113.25 187.375,111.625 187.375,110.725 R228.1@187.15,110.5 187.15,109.5 187,109.35 R226.2@187,108.05 R227.2@190,108.05
  BOTTOM w0.5: v1(189.595,113.25) Q209.G@189.595,115.1
N00300100: C281.2 IC212.4 R260.2 | length 17.5
  BOTTOM w0.25: IC212.4@272.075,104.95 272.075,104.05 272.875,103.25 274.75,103.25 275.25,103.75 275.25,107.05 275.5,107.3 R260.2@276.5,107.3 277.625,107.3 277.875,107.55 277.875,111.05 278.125,111.3 C281.2@281,111.3
N00300102: C283.1 IC212.13 | length 5.8
  BOTTOM w0.25: C283.1@267.75,108.85 270.85,108.85 272.075,110.075 IC212.13@272.075,111.05
N00300103: C282.2 IC212.1 | length 8.1
  BOTTOM w0.25: IC212.1@274.025,104.95 274.025,108.025 275.5,109.5 275.5,111.35 275.75,111.6 C282.2@276.5,111.6
N00300104: C282.1 IC212.3 | length 10.1
  BOTTOM w0.25: IC212.3@272.725,104.95 272.725,104.125 273.1,103.75 274.5,103.75 274.75,104 274.75,108 275.625,108.875 276.25,108.875 276.5,109.125 C282.1@276.5,109.9
N00300105: C284.1 IC212.14 | length 3.2
  BOTTOM w0.25: IC212.14@272.725,111.05 272.725,113.15 272.975,113.4 C284.1@273.75,113.4
N00300106: C284.2 IC212.16 | length 5.2
  BOTTOM w0.25: C284.2@273.75,115.1 274.525,115.1 274.75,114.875 274.75,112.75 274.025,112.025 IC212.16@274.025,111.05
N00300107: IC212.6 PC206.3 R288.2 | length 11.9
  BOTTOM w0.25: R288.2@267.5,100.4 268.125,100.4 ; PC206.3@269.865,97.35 269.865,98.75 269.615,99 268.875,99 268.375,99.5 268.375,100.15 ; IC212.6@270.775,104.95 270.775,103.25 270.525,103 268.875,103 268.375,102.5 268.375,100.65 ; 268.125,100.4 268.375,100.15 ; 268.125,100.4 268.375,100.65 ; 268.375,100.15 268.375,100.65
N00300108: IC212.5 PC205.3 R289.2 | length 12.2
  BOTTOM w0.25: IC212.5@271.425,104.95 271.425,103.95 272.625,102.75 272.625,100.625 272.85,100.4 R289.2@273.75,100.4 273.75,99.375 274,99.125 275,99.125 276.125,98 277.5,98 277.865,97.635 PC205.3@277.865,97.35
N00300109: IC212.10 R290.1 | length 10.2
  TOP w0.25: v1(270.125,109.875) 270.75,109.25 v1(270.75,102.1)
  BOTTOM w0.25: v1(270.125,109.875) IC212.10@270.125,111.05 ; v1(270.75,102.1) R290.1@271.75,102.1
N00300112: R248.2 R249.1 | length 2
  BOTTOM w0.25: R249.1@113.75,102.1 R248.2@115.75,102.1
N00300120: R251.2 R252.1 | length 2.1
  BOTTOM w0.25: R252.1@120.25,98.35 R251.2@120.25,100.4
N00300121: R203.1 R204.2 | length 2
  TOP w0.25: R204.2@69.35,110.5 R203.1@69.35,112.5
N00300123: IC213.3 IC214.6 | length 2.3
  TOP w0.25: IC214.6@187.9,95.115 188.985,95.115 189,95.1 IC213.3@190.225,95.1
N00300124: IC213.1 IC214.7 | length 2.3
  TOP w0.25: IC214.7@187.9,96.385 189,96.385 189.015,96.4 IC213.1@190.225,96.4
N00300126: Q217.3 R264.1 | length 4.5
  TOP w0.25: R264.1@64.35,122 66.25,122 66.45,122.2 Q217.3@66.45,124.5
N00300127: PC201.6 Q217.1 | length 52.4
  TOP w0.25: Q217.1@68.55,123.85 Q217.1@68.6,123.85 70.525,123.85 71,123.375 v1(71,117.75)
  BOTTOM w0.25: v1(71,117.75) 89,117.75 90.375,116.375 90.375,102.125 90.625,101.875 93.125,101.875 93.75,101.25 93.75,100.25 95.125,98.875 97.02,98.875 97.27,98.625 PC201.6@97.27,97.6
N00300131: PC201.3 R266.1 R267.1 | length 4.6
  BOTTOM w0.25: PC201.3@94.715,90.9 94.715,89.91 95.15,89.475 R266.1@95.15,88.5 R267.1@95.15,86.5
N00300134: Q218.6 R267.2 | length 19
  TOP w0.25: v1(97.875,86.5) 99.625,88.25 110.875,88.25 v1(112.75,86.375)
  BOTTOM w0.25: R267.2@96.85,86.5 v1(97.875,86.5) ; Q218.6@111.775,87.1 112.5,87.1 112.75,86.85 v1(112.75,86.375)
N00300136: Q218.3 R269.1 R272.1 | length 10.2
  TOP w0.25: v1(101.85,87.5) v1(106.85,87.5)
  BOTTOM w0.25: R269.1@101.85,86.5 v1(101.85,87.5) ; R272.1@106.85,86.5 v1(106.85,87.5) 107.75,87.5 108.65,88.4 Q218.3@109.725,88.4
N00300138: PC202.2 R270.2 R271.1 | length 42
  TOP w0.25: v1(69.35,116.5) R270.2@69.35,117.5
  BOTTOM w0.25: v1(69.35,116.5) 88.75,116.5 89.375,115.875 89.375,101.625 90.125,100.875 92.125,100.875 92.35,100.65 R271.1@92.35,100 92.35,99.2 92.15,99 PC202.2@92.15,97.6
N00300140: PC203.3 R268.1 R269.2 | length 4.6
  BOTTOM w0.25: PC203.3@99.715,90.9 99.715,89.91 100.15,89.475 R268.1@100.15,88.5 R269.2@100.15,86.5
N00300145: D217.2 R281.2 R292.1 | length 4.8
  BOTTOM w0.5: D217.2@266.5,115.35 R281.2@268.75,115.35 R292.1@268.75,117.9
N00300147: D218.2 Q220.1 R293.2 | length 4.5
  BOTTOM w0.5: Q220.1@281.65,117.95 Q220.1@281.65,117.9 281.65,116.7 281.85,116.5 D218.2@281.85,115.75 R293.2@281.85,113.5
N00300151: PC207.2 R290.2 R291.1 | length 8.2
  BOTTOM w0.25: R291.1@269.75,100.4 R290.2@271.75,100.4 271.75,98.75 272,98.5 274.9,98.5 275.15,98.25 PC207.2@275.15,97.35
N00300157: PC204.3 R272.2 R273.1 | length 4.6
  BOTTOM w0.25: PC204.3@104.715,90.9 104.715,89.875 105.15,89.44 R273.1@105.15,88.5 R272.2@105.15,86.5
N00300159: C271.1 CN203.7 CN215.1 | length 23
  TOP w0.5: C271.1@255.5,85.5 v1(258.25,85.5) ; CN203.7@271,83.5 271,87 272.27,88.27 CN215.1@272.27,89.65
  BOTTOM w0.5: v1(258.25,85.5) 269,85.5 CN203.7@271,83.5
N00300161: PC205.2 R284.2 R286.1 | length 7.6
  BOTTOM w0.25: PC205.2@277.85,90.65 277.85,89.125 278.1,88.875 279.25,88.875 279.5,88.625 R284.2@279.5,87.85 280.275,87.85 280.5,87.625 280.5,86.375 280.725,86.15 R286.1@281.5,86.15
N00300162: Q219.3 R284.1 | length 2.3
  BOTTOM w0.25: Q219.3@277.275,86.35 278.25,86.35 278.45,86.15 R284.1@279.5,86.15
N00300163: PC206.2 R285.2 R287.1 | length 7.5
  BOTTOM w0.25: PC206.2@269.85,90.65 269.85,86.375 270.075,86.15 R287.1@271,86.15 R285.2@273,86.15
N00300164: Q219.6 R285.1 | length 2.3
  BOTTOM w0.25: R285.1@273,87.85 273.9,87.85 274.1,87.65 Q219.6@275.225,87.65
N00300168: D219.2 D221.2 | length 2.2
  BOTTOM w0.5: D219.2@275.75,117.9 275.75,116.875 275.9,116.725 D221.2@275.9,115.75
N00300170: CN205.2 R5311.1 | length 14.5
  BOTTOM w0.25: CN205.2@181.75,143 181.75,139.875 182,139.625 190.229,139.625 191.15,138.704 R5311.1@191.15,137.25
N00300171: CN205.1 R5311.2 | length 12.9
  BOTTOM w0.25: CN205.1@184.25,143 184.25,140.625 184.5,140.375 190.604,140.375 192.85,138.129 R5311.2@192.85,137.25
N00300176: C270.1 CN203.2 CN214.1 | length 24.8
  TOP w0.5: CN214.1@281.98,92.6 281.98,86.77 282.5,86.25 283,86.25 ; CN203.2@283.5,83.5 283.5,85.75 ; C270.1@294.5,83.35 294.5,85.75 294,86.25 284,86.25 ; 283,86.25 284,86.25 ; 283,86.25 283.5,85.75 ; 283.5,85.75 284,86.25
N00300177: C297.1 CN204.2 CN213.1 | length 14.1
  TOP w0.5: C297.1@88.4,85 90.5,85 91.48,85.98 94.77,85.98 ; CN213.1@95.27,89.65 95.27,86.48 ; CN204.2@97,84.25 95.27,85.98 ; 94.77,85.98 95.27,85.98 ; 94.77,85.98 95.27,86.48 ; 95.27,85.98 95.27,86.48
N00300184: C298.1 CN201.4 CN211.1 | length 15.9
  TOP w0.5: CN211.1@162.65,90.23 168.62,90.23 169.25,89.6 ; CN201.4@169.75,84.5 169.75,89.1 ; C298.1@172.25,89.6 170.25,89.6 ; 169.25,89.6 169.75,89.1 ; 169.25,89.6 170.25,89.6 ; 169.75,89.1 170.25,89.6
N00300185: C299.1 CN201.5 CN212.1 | length 15.8
  TOP w0.5: CN201.5@172.25,84.5 172.25,85.875 174.355,87.98 178.75,87.98 ; C299.1@179,91.225 179,88.23 ; CN212.1@182.15,87.98 179.25,87.98 ; 178.75,87.98 179.25,87.98 ; 178.75,87.98 179,88.23 ; 179,88.23 179.25,87.98
N00300194: CN5.2 R5111.1 | length 14.5
  BOTTOM w0.25: CN5.2@181.75,263 181.75,259.875 182,259.625 190.229,259.625 191.15,258.704 R5111.1@191.15,257.25
N00300200: Q207.G R220.2 R221.2 R222.1 TP227.1 | length 10.3
  TOP w0.5: v1(173.595,113.25) 173.595,111.595 173.15,111.15 R222.1@173.15,110.5 173.15,109.65 173,109.5 R220.2@173,108.05 R221.2@176,108.05
  BOTTOM w0.5: v1(173.595,113.25) Q207.G@173.595,115.1
N00300201: CN29.1 Q5.G R13.2 R14.2 R15.1 | length 14.1
  TOP w0.5: CN29.1@179.5,242.125 181,242.125 181.5,242.625 R13.2@181.5,245.45 R14.2@184.5,245.45 186.7,245.45 R15.1@186.75,245.4
  BOTTOM w0.5: CN29.1@179.5,242.125 181.595,244.22 Q5.G@181.595,245.1
N00300202: Q6.G R16.2 R17.2 R18.1 TP26.1 | length 11.1
  TOP w0.5: v1(190.5,242.875) 189.25,244.125 R16.2@189.25,245.45 R17.2@192.25,245.45 194.05,245.45 R18.1@194.5,245.9
  BOTTOM w0.5: Q6.G@189.595,245.1 189.595,243.78 v1(190.5,242.875)
N00300203: Q7.G R20.2 R21.2 R22.1 TP27.1 | length 10.3
  TOP w0.5: v1(173.595,233.25) 173.595,231.595 173.15,231.15 R22.1@173.15,230.5 173.15,229.65 173,229.5 R20.2@173,228.05 R21.2@176,228.05
  BOTTOM w0.5: v1(173.595,233.25) Q7.G@173.595,235.1
N00300205: CN32.1 Q8.G R23.2 R24.2 R25.1 | length 10.7
  TOP w0.5: CN32.1@181.595,233.25 180.65,232.305 R25.1@180.65,230.5 180.65,229.65 180,229 R23.2@180,228.05 R24.2@183,228.05
  BOTTOM w0.5: CN32.1@181.595,233.25 Q8.G@181.595,235.1
N00300206: Q9.G R26.2 R27.2 R28.1 TP29.1 | length 11.5
  TOP w0.5: v1(189.595,233.25) 189,233.25 187.375,231.625 187.375,230.725 R28.1@187.15,230.5 187.15,229.5 187,229.35 R26.2@187,228.05 R27.2@190,228.05
  BOTTOM w0.5: v1(189.595,233.25) Q9.G@189.595,235.1
N00300213: C76.1 IC11.2 R52.2 R53.1 | length 10.3
  BOTTOM w0.25: IC11.2@121.35,211.325 120.5,211.325 120.25,211.575 R52.2@120.25,216.65 C76.1@122.25,216.65 R53.1@124.25,216.65
N00300214: C101.2 IC11.3 PC3.4 Q11.2 R50.1 | length 48.5
  BOTTOM w0.25: PC3.4@99.73,217.6 99.73,218.75 99.6,218.88 Q11.2@99.6,220.15 99.6,223.1 100.25,223.75 112.75,223.75 113,223.5 113,221.5 113.25,221.25 114.5,221.25 114.75,221 114.75,219.625 115,219.375 116.5,219.375 116.75,219.125 116.75,216.125 117.125,215.75 118.875,215.75 ; IC11.3@121.35,210.675 120.325,210.675 119.75,211.25 119.75,215.125 119.125,215.75 ; R50.1@124.25,220.4 C101.2@122.25,220.4 121.5,220.4 121.25,220.15 121.25,217.75 121,217.5 119.75,217.5 119.125,216.875 119.125,216 ; 118.875,215.75 119.125,215.75 ; 118.875,215.75 119.125,216 ; 119.125,215.75 119.125,216
N00300221: C80.1 IC11.6 R58.2 R59.1 | length 16
  BOTTOM w0.25: R58.2@111.75,220.4 111.75,218.6 112,218.35 112.5,218.35 ; IC11.6@115.15,210.675 113.575,210.675 112.75,211.5 112.75,218.1 ; R59.1@115.75,218.35 C80.1@113.75,218.35 113,218.35 ; 112.5,218.35 112.75,218.1 ; 112.5,218.35 113,218.35 ; 112.75,218.1 113,218.35
N00300222: C79.2 IC11.5 PC4.4 Q12.2 R57.1 | length 27.4
  BOTTOM w0.25: PC4.4@104.73,217.6 104.73,218.52 104.5,218.75 102.85,218.75 102.6,219 Q12.2@102.6,220.15 102.6,221 102.85,221.25 107.5,221.25 107.75,221 C79.2@107.75,220.4 R57.1@109.75,220.4 109.75,215.5 109.25,215 109.25,214 113.225,210.025 IC11.5@115.15,210.025
N00300225: C13.2 IC1.8 R1.1 R64.2 | length 13.6
  TOP w0.25: R1.1@56.8,239.75 56.8,238.575 57.275,238.1 C13.2@57.275,236.75 IC1.8@60.4,236.75 61.25,236.75 61.375,236.875 61.375,241.75 61.625,242 R64.2@62.65,242
N00300229: D2.2 D3.2 D4.2 IC2.3 R11.1 R14.1 R17.1 | length 43.6
  TOP w0.5: R11.1@176.75,247.55 176.75,248.35 177.4,249 D2.2@177.4,250.5 177.4,252 177.65,252.25 184.9,252.25 ; R14.1@184.5,247.55 184.5,248.35 185.15,249 D3.2@185.15,250.5 185.15,252 ; R17.1@192.25,247.55 192.25,248.35 192.9,249 D4.2@192.9,250.5 ; IC2.3@197.365,240.1 197.365,247.385 194.25,250.5 D4.2@192.9,250.5 ; 184.9,252.25 185.15,252 ; 184.9,252.25 185.4,252.25 ; 185.15,252 185.4,252.25 ; 185.4,252.25 192.65,252.25 192.9,252 D4.2@192.9,250.5
N00300231: IC2.5 IC13.6 | length 20.3
  TOP w0.25: IC13.6@192.275,216.4 193.25,216.4 193.5,216.65 193.5,229.375 196.25,232.125 196.25,233.5 196.095,233.655 IC2.5@196.095,234.4
N00300232: C41.1 C436.1 D5.2 IC2.2 | length 17.5
  TOP w0.5: C41.1@197.225,256.25 197.225,254.425 196.55,253.75 D5.2@196.55,252.5 196.55,250.01 198.944,247.616 C436.1@198.944,243.426 198.944,241.776 198.635,241.467 IC2.2@198.635,240.1
N00300233: IC2.6 IC13.4 | length 22.3
  TOP w0.25: IC13.4@192.275,215.1 193.75,215.1 194,215.35 194,229.125 197.365,232.49 IC2.6@197.365,234.4
N00300234: C14.1 IC1.15 | length 2.4
  TOP w0.25: IC1.15@65.1,239.75 C14.1@67.525,239.75
N00300240: C16.1 C17.1 IC1.1 L1.1 R8.2 | length 72.6
  TOP w0.25: v1(58.625,241.625) 58.625,241.25 59.625,240.25 IC1.1@60.4,240.25
  TOP w1: 73.15,242.7 L1.1@80.5,242.7 ; 80.5,240.15 L1.1@80.5,242.7 ; v1@80.5,245.25 v1(80.5,245.125) L1.1@80.5,242.7 ; 81,217.5 85.15,217.5 ; 81,232.5 85.15,232.5 ; 85.15,213.043 85.15,217.5 ; 85.15,221.957 85.15,217.5 ; 85.15,228.043 85.15,232.5 ; 85.15,236.957 85.15,232.5 ; 87.85,242.7 L1.1@80.5,242.7 ; 89,217.5 C17.1@86.3,217.5 85.15,217.5 ; 89,232.5 C16.1@86.3,232.5 85.15,232.5
  BOTTOM w0.25: v1(58.625,241.625) 61.5,244.5 61.5,254.25 61.75,254.5 R8.2@64,254.5
  other v1: 82.5,210.375 88.5,210.375 81.5,211.25 83.5,211.25 85.5,211.25 87.5,211.25 82.5,212.25 84.5,212.25 86.5,212.25 88.5,212.25 81.5,213.25 83.5,213.25 85.5,213.25 87.5,213.25 82.5,214.25 82.5,220.25 81.5,221.25 82.5,222.25 84.5,222.25 86.5,222.25 88.5,222.25 81.5,223.25 83.5,223.25 85.5,223.25 87.5,223.25 82.5,224.25 84.5,224.25 86.5,224.25 88.5,224.25 81.5,225.25 83.5,225.25 85.5,225.25 87.5,225.25 82.5,226.25 84.5,226.25 86.5,226.25 88.5,226.25 81.5,227.25 83.5,227.25 85.5,227.25 87.5,227.25 82.5,228.25 84.5,228.25 86.5,228.25 88.5,228.25 81.5,229.25 81.5,235.25 62.5,245.125 64.5,245.125 70.5,245.125 72.5,245.125 74.5,245.125 76.5,245.125 78.5,245.125 82.5,245.125 84.5,245.125 86.5,245.125 88.5,245.125 63.5,246 65.5,246 71.5,246 73.5,246.125 75.5,246.125 77.5,246.125 79.5,246.125 81.5,246.125 83.5,246.125 85.5,246.125 87.5,246.125 62.5,247 64.5,247 66.5,247 68.5,247 70.5,247 72.5,247 74.5,247.125 76.5,247.125 78.5,247.125 80.5,247.125 82.5,247.125 84.5,247.125 86.5,247.125 88.5,247.125 63.5,248 65.5,248 67.5,248 69.5,248 71.5,248 73.5,248.125 75.5,248.125 77.5,248.125 79.5,248.125 81.5,248.125 83.5,248.125 85.5,248.125 87.5,248.125 62.5,249 64.5,249 66.5,249 68.5,249 70.5,249 63.5,250 65.5,250 67.5,250 69.5,250 71.5,250 62.5,251 64.5,251 66.5,251 68.5,251 70.5,251 67.5,252 69.5,252 71.5,252 68.5,253 70.5,253 67.5,254 69.5,254 71.5,254 68.5,255 70.5,255 67.5,256 69.5,256 71.5,256 68.5,257 70.5,257 63.5,258 65.5,258 67.5,258 69.5,258 71.5,258 62.5,259 64.5,259 66.5,259 68.5,259 70.5,259
N00300241: IC1.2 IC1.5 Q1.S Q2.S R7.2 R8.1 | length 44.3
  TOP w0.25: 54.1,248.975 R7.2@54.1,249.75 ; 54.1,250.525 R7.2@54.1,249.75 ; 54.925,249.75 R7.2@54.1,249.75 ; v1(58.625,238.875) 59.25,238.25 IC1.5@60.4,238.25 ; v1(58.625,240.25) 59.125,239.75 IC1.2@60.4,239.75
  BOTTOM w0.25: R8.1@58,254 60.25,254 60.5,253.75 60.5,245.5 57.25,242.25 57.25,240.25 v1(58.625,238.875) ; R8.1@58,254.5 60.5,254.5 61,254 61,245 57.875,241.875 57.875,241 v1(58.625,240.25)
  other v1: 55.5,250 57.5,250 59.5,250 54.5,251 56.5,251 58.5,251 53.5,252 54.5,253 54.5,255 53.5,256 52.5,257 54.5,257 53.5,258 55.5,258 57.5,258 59.5,258 52.5,259 54.5,259 56.5,259 58.5,259
N00300242: D322.2 IC1.6 Q1.G Q2.G R7.1 R434.1 | length 35.1
  TOP w0.25: v1(52.4,254.595) R7.1@52.4,249.75 v1(52.4,248.095) 57.625,248.095 57.875,247.845 57.875,238.25 58.625,237.5 59.375,237.5 59.625,237.75 IC1.6@60.4,237.75
  TOP w0.5: v1(52.4,248.095) 53.767,246.728 55.56,246.728 55.975,246.313 R434.1@55.975,244.95 55.975,243.88 55.775,243.68 D322.2@55.775,242.727
  BOTTOM w0.25: Q2.G@51.15,248.095 v1(52.4,248.095) ; Q1.G@51.15,254.595 v1(52.4,254.595)
N00300243: D7.1 R23.1 | length 3.7
  TOP w0.5: D7.1@179.35,222.5 179.35,223.725 180,224.375 R23.1@180,225.95
N00300244: D5.1 R9.2 | length 3
  TOP w0.5: D5.1@200.95,252.5 200.95,251 201,250.95 R9.2@201,249.55
N00300245: D2.1 R10.1 | length 3.2
  TOP w0.5: D2.1@173.1,250.5 173.1,249 173.75,248.35 R10.1@173.75,247.55
N00300246: C42.1 CN30.1 Q4.D Q5.D Q6.D R29.2 R401.1 TP4.1 TP6.1 | length 46.8
  TOP w0.5: 174.439,253.439 TP4.1@175.5,254.5 ; 174.439,255.561 TP4.1@175.5,254.5 ; 176.561,253.439 TP4.1@175.5,254.5 ; 176.561,255.561 TP4.1@175.5,254.5 ; 182.581,253.581 CN30.1@183.5,254.5 ; 182.581,255.419 CN30.1@183.5,254.5 ; 184.419,253.581 CN30.1@183.5,254.5 ; 184.419,255.419 CN30.1@183.5,254.5 ; 190.439,253.439 TP6.1@191.5,254.5 ; 190.439,255.561 TP6.1@191.5,254.5 ; 192.561,253.439 TP6.1@191.5,254.5 ; 192.561,255.561 TP6.1@191.5,254.5
  TOP w1: R401.1@169.35,258.5 169.35,257.9 169.5,257.75 v1(169.5,256)
  Mid-Layer 1 w0.5: 182.581,253.581 CN30.1@183.5,254.5 ; 182.581,255.419 CN30.1@183.5,254.5 ; 184.419,253.581 CN30.1@183.5,254.5 ; 184.419,255.419 CN30.1@183.5,254.5
  Mid-Layer 2 w0.5: 182.581,253.581 CN30.1@183.5,254.5 ; 182.581,255.419 CN30.1@183.5,254.5 ; 184.419,253.581 CN30.1@183.5,254.5 ; 184.419,255.419 CN30.1@183.5,254.5
  Mid-Layer 3 w0.5: 182.581,253.581 CN30.1@183.5,254.5 ; 182.581,255.419 CN30.1@183.5,254.5 ; 184.419,253.581 CN30.1@183.5,254.5 ; 184.419,255.419 CN30.1@183.5,254.5
  BOTTOM w0.25: C42.1@167.25,251.85 167.25,255.75 167.5,256 v1(169.5,256)
  BOTTOM w0.5: 182.581,253.581 CN30.1@183.5,254.5 ; 182.581,255.419 CN30.1@183.5,254.5 ; 184.419,253.581 CN30.1@183.5,254.5 ; 184.419,255.419 CN30.1@183.5,254.5
  other v1: 173.5,254.5 178.5,255.5 180.5,255.5 186.5,255.5 188.5,255.5 173.5,256.5 175.5,256.5 177.5,256.5 179.5,256.5 181.5,256.5 183.5,256.5 185.5,256.5 187.5,256.5 189.5,256.5 172.5,257.5 174.5,257.5 176.5,257.5 178.5,257.5 180.5,257.5 182.5,257.5 184.5,257.5 186.5,257.5 188.5,257.5 173.5,258.5 175.5,258.5 177.5,258.5 179.5,258.5 181.5,258.5 183.5,258.5 185.5,258.5 187.5,258.5 189.5,258.5
N00300247: D3.1 R13.1 | length 3.2
  TOP w0.5: D3.1@180.85,250.5 180.85,249 181.475,248.375 181.5,248.375 R13.1@181.5,247.55
N00300248: D4.1 R16.1 | length 3.2
  TOP w0.5: D4.1@188.6,250.5 188.6,249 189.25,248.35 R16.1@189.25,247.55
N00300249: D6.1 R20.1 | length 3.7
  TOP w0.5: D6.1@172.35,222.5 172.35,223.725 173,224.375 R20.1@173,225.95
N00300250: D8.1 R26.1 | length 3.7
  TOP w0.5: D8.1@186.35,222.5 186.35,223.725 187,224.375 R26.1@187,225.95
N00300258: C440.1 CN21.1 D19.1 D20.1 Q13.1 Q14.1 Q15.1 Q16.1 Q20.3 R63.2 R92.2 | length 75.9
  TOP w0.5: v1(283.25,234.125) 292.75,234.125 293.25,234.625 Q14.1@293.25,236.3 v1(294.875,236.3) ; Q13.1@293.25,247.8 v1(294.875,247.8) ; v1(298.125,244.7) Q16.1@299.75,244.7 ; Q15.1@299.75,256.2 v1(298.125,256.2) 298.125,257 ; 298.125,257 298.812,257.687 299,257.875 299,258.375 CN21.1@298.125,258.375 ; 298.125,257 297.438,257.687 297.25,257.875 297.25,258.375 CN21.1@298.125,258.375 ; 298.125,257 CN21.1@298.125,258.375
  BOTTOM w0.5: R92.2@268.75,239.6 270.405,239.6 ; C440.1@270.405,241.775 270.405,239.6 ; v1(283.25,234.125) 283.25,239.55 282.75,240.05 279.7,240.05 279.25,239.6 R63.2@277.75,239.6 D19.1@275.75,239.6 D20.1@273.5,239.6 270.405,239.6 ; v1(294.875,236.3) 296,236.3 296.5,236.8 296.5,244.2 ; v1(294.875,247.8) 296,247.8 ; v1(298.125,244.7) 297,244.7 ; v1(298.125,256.2) 297,256.2 296.5,255.7 296.5,248.3 ; 296,247.8 296.5,247.3 ; 296,247.8 296.5,248.3 ; 296.5,244.2 297,244.7 ; 296.5,244.2 296.5,245.2 ; 296.5,245.2 296.5,247.3 ; 296.5,245.2 297,244.7 ; 296.5,247.3 296.5,248.3
N00300259: CN22.1 D18.1 D21.1 Q13.2 Q14.2 Q15.2 Q16.2 Q20.2 R63.1 | length 31
  TOP w0.5: v1(277.6,233.25) 294,233.25
  TOP w1: 294.65,234 CN22.1@298,234 298,235.75
  BOTTOM w0.5: v1(277.6,233.25) D21.1@277.6,235.75 ; R63.1@277.75,237.9 277.75,236.875 277.6,236.725 D21.1@277.6,235.75 ; Q20.2@280.35,237.95 Q20.2@280.35,237.9 280.35,236.7 280.15,236.5 D18.1@280.15,235.75 D21.1@277.6,235.75
N00300261: CN23.1 D11.2 D12.2 D13.2 R60.1 | length 8.8
  BOTTOM w0.25: R60.1@276.5,225.2 276.5,223.75 276,223.25 D11.2@276,222.1 D12.2@278.5,222.1 279.525,222.1 CN23.1@279.875,222.45 280.225,222.1 D13.2@281.25,222.1
N00300264: PC3.6 Q11.1 | length 3.7
  BOTTOM w0.25: Q11.1@100.9,220.2 Q11.1@100.9,220.15 100.9,219 101.15,218.75 102.02,218.75 102.27,218.5 PC3.6@102.27,217.6
N00300265: Q11.3 R49.2 | length 16.7
  BOTTOM w0.25: Q11.3@100.25,222.3 Q11.3@100.25,222.35 100.25,223 100.5,223.25 112.25,223.25 112.5,223 112.5,220.875 112.975,220.4 R49.2@113.75,220.4
N00300271: Q12.3 R56.2 | length 2.6
  BOTTOM w0.25: Q12.3@103.25,222.3 104.5,222.3 104.7,222.1 R56.2@105.75,222.1
N00300272: PC4.6 Q12.1 | length 4.9
  BOTTOM w0.25: Q12.1@103.9,220.2 Q12.1@103.9,220.15 103.9,219.5 104.15,219.25 104.75,219.25 106.4,217.6 PC4.6@107.27,217.6
N00300273: C15.2 IC1.11 R2.1 R3.2 | length 9.3
  TOP w0.25: IC1.11@65.1,237.75 64.375,237.75 64.125,237.5 64.125,236.5 64.375,236.25 65.35,236.25 65.6,236 R2.1@65.6,234.5 C15.2@67.65,234.5 R3.2@67.65,232.5
N00300274: IC1.9 IC1.10 PC1.4 Q17.2 R65.2 | length 61.2
  TOP w0.25: IC1.9@65.1,236.75 v1(66.25,236.75) ; IC1.10@65.1,237.25 66.125,237.25 66.25,237.125 v1(66.25,236.75) ; Q17.2@68.55,245.15 67.65,245.15 67.4,244.9 R65.2@67.4,242 67.4,241.25 67.65,241 68.25,241 68.5,240.75 68.5,237 68.25,236.75 v1(66.25,236.75)
  BOTTOM w0.25: v1(66.25,236.75) 66.625,237.125 88.875,237.125 89.875,236.125 89.875,221.875 90.375,221.375 92.875,221.375 93.25,221 93.25,220 94.73,218.52 PC1.4@94.73,217.6
N00300275: IC1.13 R70.1 | length 3.5
  TOP w0.25: IC1.13@65.1,238.75 66.25,238.75 66.5,238.5 66.5,237.75 66.75,237.5 R70.1@67.65,237.5
N00300286: D20.2 R82.2 | length 4.5
  BOTTOM w0.5: R82.2@271,235.8 271,237.65 271.25,237.9 D20.2@273.5,237.9
N00300287: IC12.12 R81.1 R82.1 | length 5.1
  BOTTOM w0.25: R82.1@271,233.7 271,232.675 271.425,232.25 IC12.12@271.425,231.05
  BOTTOM w0.5: R81.1@268.75,233.65 269.625,233.65 269.675,233.7 R82.1@271,233.7
N00300293: C81.2 IC12.4 R60.2 | length 17.5
  BOTTOM w0.25: IC12.4@272.075,224.95 272.075,224.05 272.875,223.25 274.75,223.25 275.25,223.75 275.25,227.05 275.5,227.3 R60.2@276.5,227.3 277.625,227.3 277.875,227.55 277.875,231.05 278.125,231.3 C81.2@281,231.3
N00300296: C83.1 IC12.13 | length 5.8
  BOTTOM w0.25: C83.1@267.75,228.85 270.85,228.85 272.075,230.075 IC12.13@272.075,231.05
N00300297: C82.2 IC12.1 | length 8.1
  BOTTOM w0.25: IC12.1@274.025,224.95 274.025,228.025 275.5,229.5 275.5,231.35 275.75,231.6 C82.2@276.5,231.6
N00300298: C82.1 IC12.3 | length 10.1
  BOTTOM w0.25: IC12.3@272.725,224.95 272.725,224.125 273.1,223.75 274.5,223.75 274.75,224 274.75,228 275.625,228.875 276.25,228.875 276.5,229.125 C82.1@276.5,229.9
N00300299: C84.1 IC12.14 | length 3.2
  BOTTOM w0.25: IC12.14@272.725,231.05 272.725,233.15 272.975,233.4 C84.1@273.75,233.4
N00300300: C84.2 IC12.16 | length 5.2
  BOTTOM w0.25: C84.2@273.75,235.1 274.525,235.1 274.75,234.875 274.75,232.75 274.025,232.025 IC12.16@274.025,231.05
N00300301: IC12.10 R90.1 | length 10.2
  TOP w0.25: v1(270.125,229.875) 270.75,229.25 v1(270.75,222.1)
  BOTTOM w0.25: v1(270.125,229.875) IC12.10@270.125,231.05 ; v1(270.75,222.1) R90.1@271.75,222.1
N00300302: IC12.6 PC6.3 R88.2 | length 11.9
  BOTTOM w0.25: R88.2@267.5,220.4 268.125,220.4 ; PC6.3@269.865,217.35 269.865,218.75 269.615,219 268.875,219 268.375,219.5 268.375,220.15 ; IC12.6@270.775,224.95 270.775,223.25 270.525,223 268.875,223 268.375,222.5 268.375,220.65 ; 268.125,220.4 268.375,220.15 ; 268.125,220.4 268.375,220.65 ; 268.375,220.15 268.375,220.65
N00300303: IC12.5 PC5.3 R89.2 | length 12.2
  BOTTOM w0.25: IC12.5@271.425,224.95 271.425,223.95 272.625,222.75 272.625,220.65 272.875,220.4 R89.2@273.75,220.4 273.75,219.375 274,219.125 275,219.125 276.125,218 277.625,218 277.865,217.76 PC5.3@277.865,217.35
N00300315: R48.2 R49.1 | length 2
  BOTTOM w0.25: R49.1@113.75,222.1 R48.2@115.75,222.1
N00300316: R51.2 R52.1 | length 2.1
  BOTTOM w0.25: R52.1@120.25,218.35 R51.2@120.25,220.4
N00300317: R3.1 R4.2 | length 2
  TOP w0.25: R4.2@69.35,230.5 R3.1@69.35,232.5
N00300319: IC13.3 IC14.6 | length 2.3
  TOP w0.25: IC14.6@187.9,215.115 188.985,215.115 189,215.1 IC13.3@190.225,215.1
N00300320: IC13.1 IC14.7 | length 2.3
  TOP w0.25: IC14.7@187.9,216.385 189,216.385 189.015,216.4 IC13.1@190.225,216.4
N00300322: Q17.3 R64.1 | length 4.5
  TOP w0.25: R64.1@64.35,242 66.25,242 66.45,242.2 Q17.3@66.45,244.5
